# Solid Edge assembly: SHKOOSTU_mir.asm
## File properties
Author: Türk
Template: Iso Assembly.asm
Last saved by: Türk
Revision: 4
Application: Solid Edge
Username: Türk
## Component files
Shockabsorber.par
ShKolvikoostu.asm
Shkaan.par
Poldikoostu5.asm
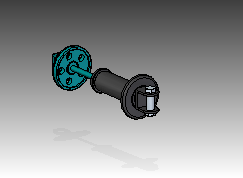
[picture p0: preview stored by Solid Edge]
